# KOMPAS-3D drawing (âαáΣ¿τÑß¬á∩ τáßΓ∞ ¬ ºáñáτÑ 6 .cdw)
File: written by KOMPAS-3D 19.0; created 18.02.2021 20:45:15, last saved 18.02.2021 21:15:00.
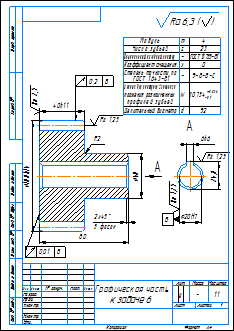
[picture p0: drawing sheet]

Sheet 1: A4, portrait

Document properties: Автор: Юрий; Знак неуказанной шероховатости: 4; Параметр неуказанной шероховатости: Ra 6,3

Title block, sheet 1: Наименование: Графическая часть / к задаче 6; Количество листов документа: 1; Форматы листов документа: A4; Литера: у; stored path: C:\Users\Юрий\Desktop\метрология сироп\Графическая часть к задаче 6 .cdw

Views: Вид 1, Вид по стрелке А
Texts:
  Ra 1,25
  Ra 2,5
  Модуль
  Число зубьев
  Номинальный исходный контур
  ГОСТ 13755-81
  Коэффициент смещения
  Степень точности по
  ГОСТ 1643-81
  Данные для контроля взаимного
  поожения разноименных
  профилей зубьев
  Делительный диаметр
  Ra 6,3
  Ra 6,3 ( )
Dimensions and other numbers on the sheet: 6; 24,8; 20; 40; 2; 5 фасок; 80; 100; 0,2; 0,01; 4; 23; 0; 9-8-8-С; 30,754 +0,036 -0,1; 92; 9; 1:1; 1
